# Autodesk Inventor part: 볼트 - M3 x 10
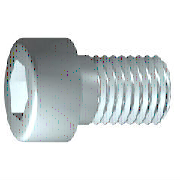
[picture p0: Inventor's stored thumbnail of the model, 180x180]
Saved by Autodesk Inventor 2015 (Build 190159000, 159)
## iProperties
Created: 2012-02
Part Number: 볼트 - M3 x 10
Material: 스테인리스강
Description: 6각 소켓 머리 캡 나사
Document SubType Name: Modeling
Standard: ISO 4762
Designer: mduedu
Standard Revision: Fourth edition 2004-03-01
Standards Organization: ISO
Language: ko-KR
Size Designation: M3 x 10
Categories: <MemberInstance><Categories><Category DisplayName="조임쇠" InternalName="e4da775c-781d-43d5-af7c-5136215cf5a6" Mnemonic="FSTN"><Category DisplayName="볼트" InternalN
Density: 7.75 g/cm^3
Appearance: 반광택
IsCustomPart: 0
Author: mduedu
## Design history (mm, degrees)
sketch "스케치1"
  geometry: L1 (-0.867, 0)-(10, 0); L2 (10, 0)-(10, 1.5); L3 (10, 1.5)-(1.25, 1.5); L4 (1.25, 1.5)-(0.943, 1.5); L5 (0.943, 1.5)-(0, 1.5); L6 (0, 1.5)-(0, 2.75); L7 (0, 2.75)-(-3, 2.75); L8 (-3, 2.75)-(-3, 1.443); L9 (-3, 1.443)-(-1.7, 1.443); L10 (-1.7, 1.443)-(-0.867, 0); L11 (-5.6, 0)-(12.6, 0) reference; L12 (0, -0.55)-(0, 3.3) reference; L13 (1.25, 1.5)-(0, 1.5)
  constraints: 22 end point, 6 parallel, 2 collinear, 2 perpendicular, 1 horizontal, 1 point on line
  dimensions: "d1" = 8.75 distance from line of L3.end L2 (= GEL); "d2" = 0.30683 distance of L4.end L3.end (computed from GAL); "d3" = 3 distance between parallel lines of L8 L6 (= KOH); "d4" = 1.3 distance of L8.end L9.end (= INTI); "d5" = 60 deg angle of L10 L1; "d6" = 3 diameter of L3 L1 (= GD); "d7" = 3 diameter of L5 L1 (= BDM); "d8" = 2.88675 diameter of L9 L1 (= 1.1547 x SW); "d9" = 5.5 diameter of L7 L1 (= KOD); "d26" = 10 distance between parallel lines of L12 L2 (= NLG)
revolve "본체" sketch "스케치1" stored, may be unused: angle "d10" = 90 deg
sketch "스케치2"
  geometry: L1 (0, -3.85)-(0, 3.85) reference; L2 (-3.85, 0)-(3.85, 0) reference; L3 (1.443, 0)-(0.722, -1.25); L4 (0.722, -1.25)-(-0.722, -1.25); L5 (-0.722, -1.25)-(-1.443, 0); L6 (-1.443, 0)-(-0.722, 1.25); L7 (-0.722, 1.25)-(0.722, 1.25); L8 (0.722, 1.25)-(1.443, 0); 2 further points
  constraints: 12 end point, 1 coincident, 1 horizontal alignment, 1 point on line, 12 other
extrude "슬롯" join sketch "스케치2" stored distance "d11" = 10; taper "d12" = 0 deg
workplane "Work Plane1"
fillet "Fillet2" dims "d30" = 0.1 (= R)
body "Solid1"
fillet "모깎기1" dims "d17" = 0.3 (= RR)
feature "스레드" dims "d13" = 8.75 (= GEL), "d14" = 0
chamfer "모따기1" distance "d15" = 0.30673 (= -0.5 x SPD + 0.5 x GD); stored, may be unused: second distance "d16" = 0.30673 (= GUL), angle "d27" = 45 deg
other parameters: "GD" = 3 [user parameter; used in 2 equation terms], "NLG" = 10 [user parameter; used in 1 equation term], "GEL" = 8.75 [user parameter; used in 2 equation terms], "KOD" = 5.5 [user parameter; used in 1 equation term], "KOH" = 3 [user parameter; used in 1 equation term], "INTI" = 1.3 [user parameter; used in 1 equation term], "GAL" = 0.30673 (= 0.61345 x PTC) [user parameter; used in 1 equation term], "GUL" = 0.30673 (= 0.61345 x PTC) [user parameter; used in 1 equation term], "BDM" = 3 (= NND) [user parameter; used in 1 equation term], "SW" = 2.5 [user parameter; used in 2 equation terms], "RR" = 0.3 [user parameter; used in 1 equation term], "SPD" = 2.38655 (= NND - 1.2269 x PTC) [user parameter; used in 1 equation term], "d19" = 0, "d28" = 0, "d29" = 0, "R" = 0.1 [user parameter; used in 1 equation term], "TOA" = 30 deg [user parameter], "GD1" = 2.38655 (= THREADDIA - 1.2269 x PTC) [user parameter], "THREADDIA" = 3 [user parameter; used in 1 equation term], "FAWI" = 45 deg [user parameter], "PTC" = 0.5 [user parameter; used in 5 equation terms], "NND" = 3 [user parameter; used in 2 equation terms], "E0" = 2.8875 (= 1.155 x SW) [user parameter]
